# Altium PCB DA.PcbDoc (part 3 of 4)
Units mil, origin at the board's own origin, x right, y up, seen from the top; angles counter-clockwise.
Board outline 6588.03 x 5423.03 mil, 4 copper layers (Top Layer, GND, VCC, Bottom Layer); 506 components, 345 nets, 1676 pads, 350 vias.
Unrouted connection lines stored in the file: 30.
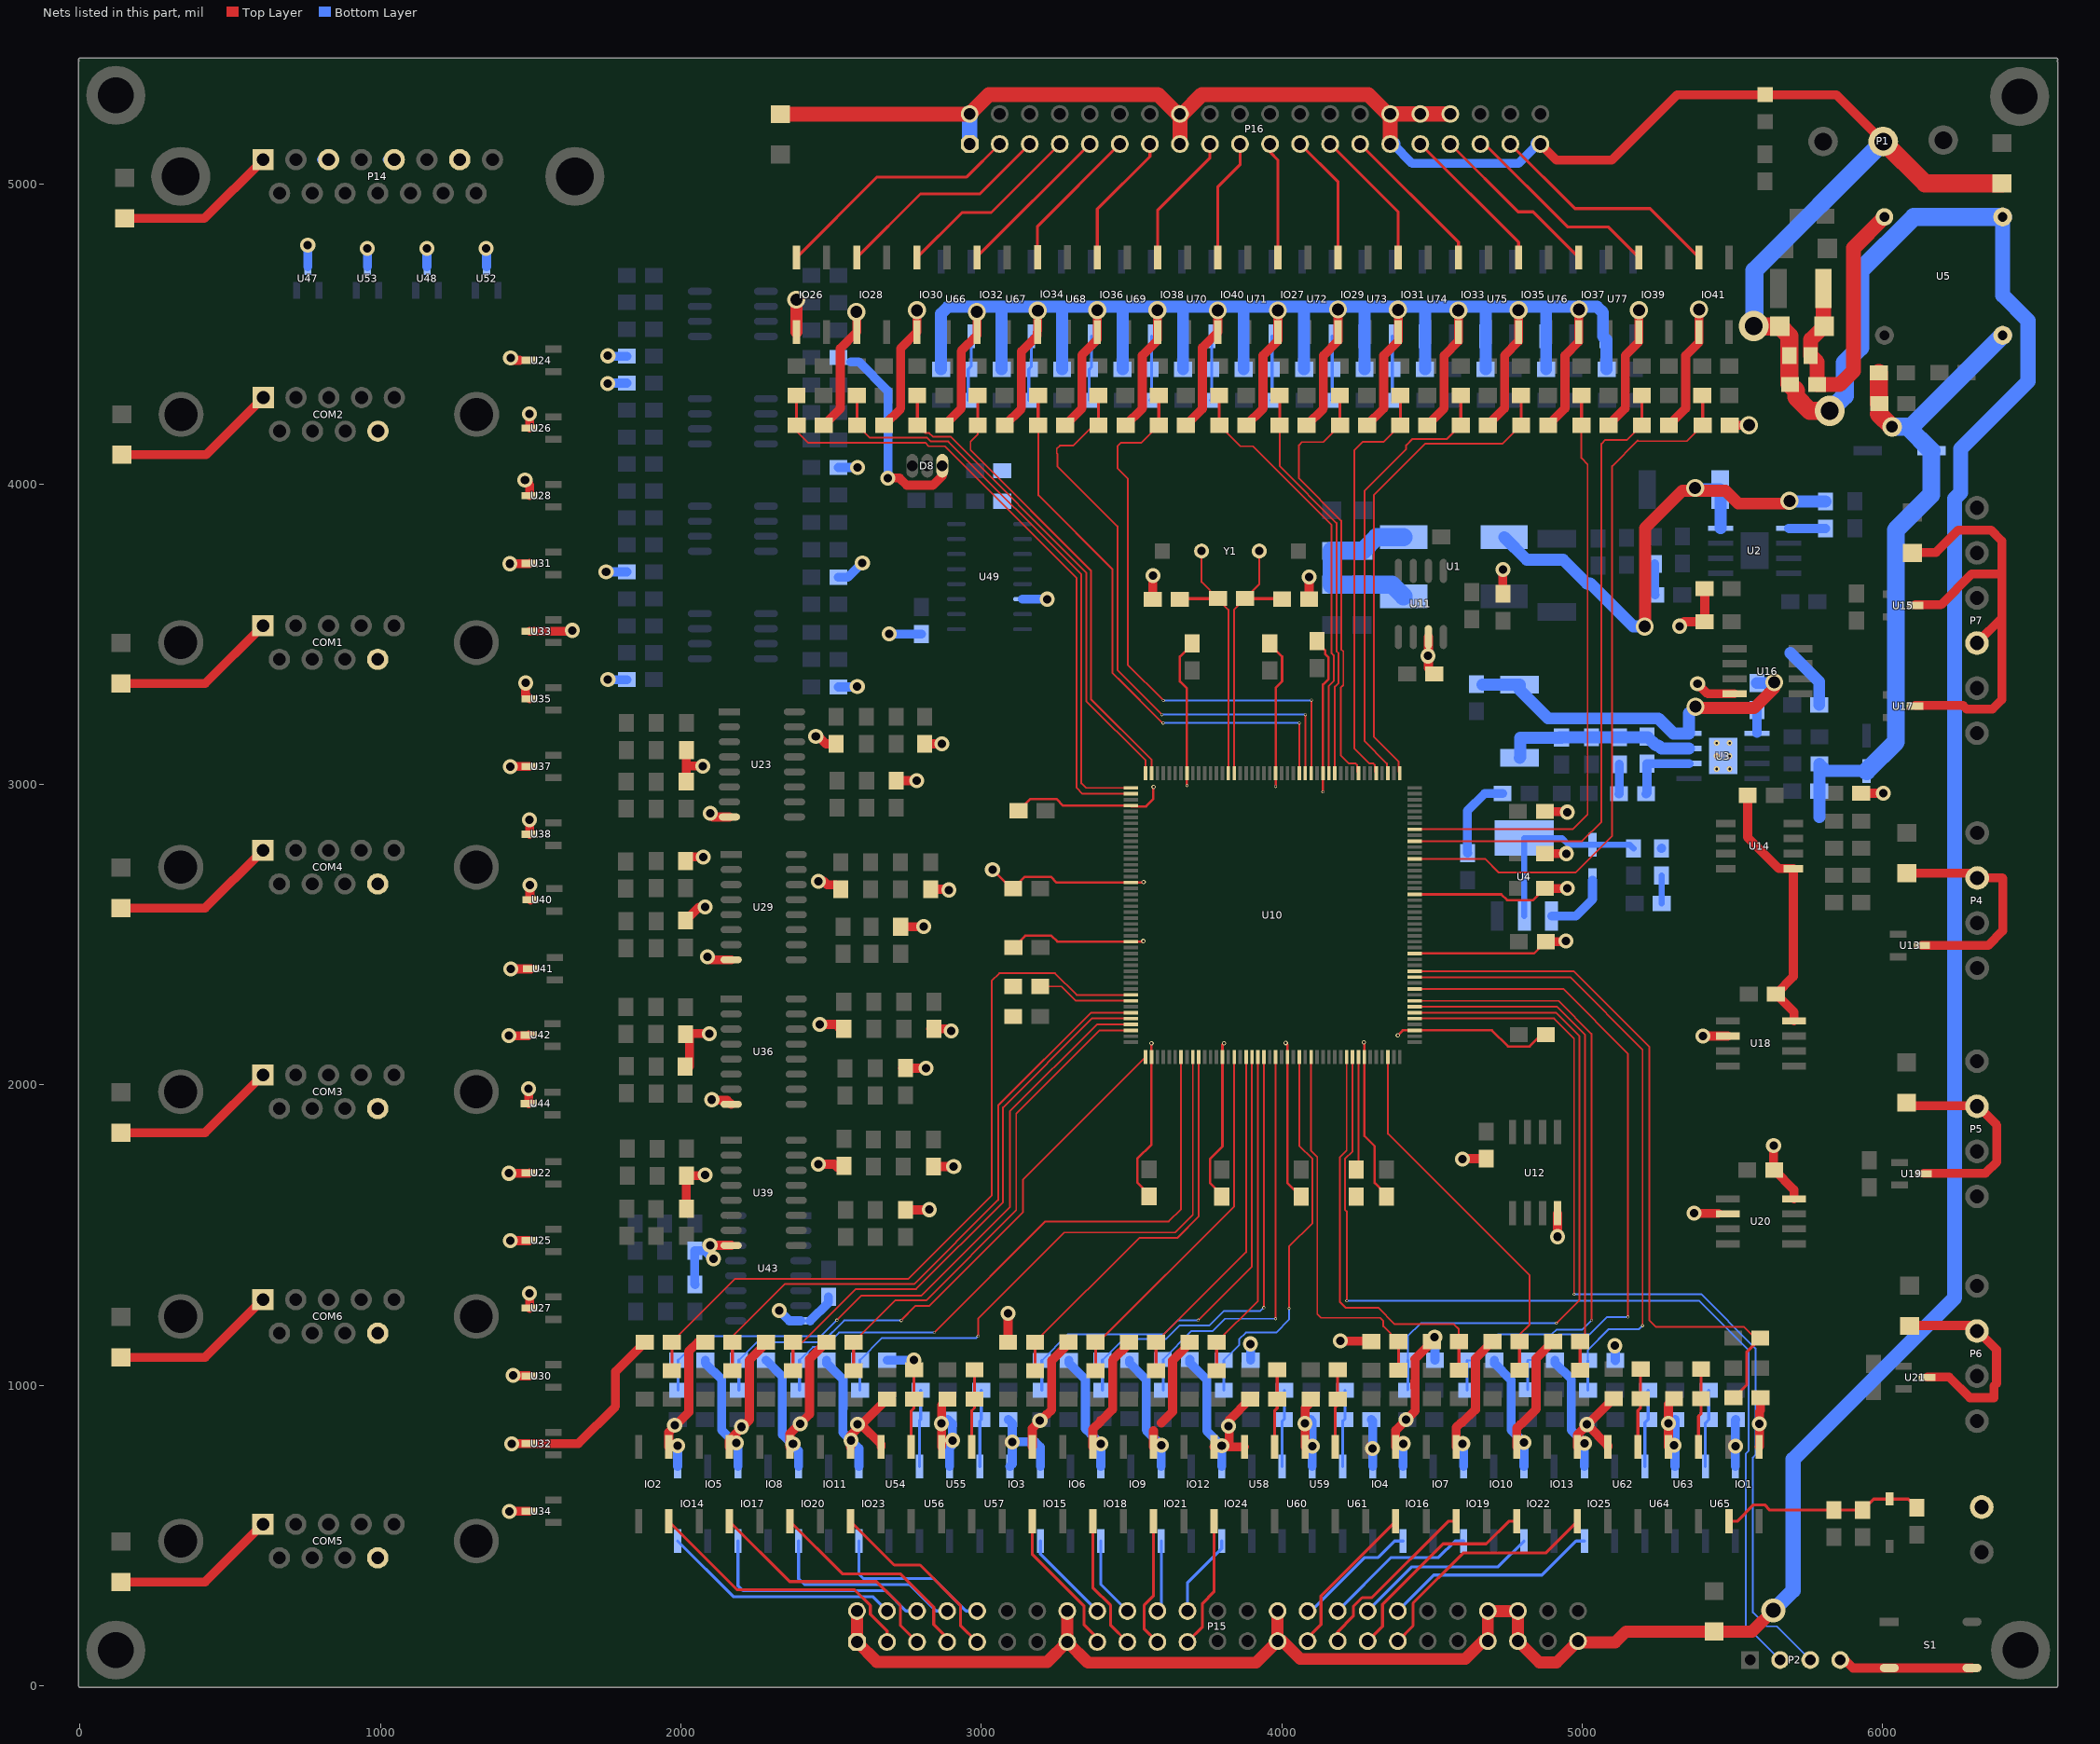
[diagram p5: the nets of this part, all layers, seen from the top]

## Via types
v1: diameter 10, hole 6, Top Layer to Bottom Layer, 112 vias
v2: diameter 50, hole 28, Top Layer to GND, 68 vias
v3: diameter 50, hole 28, Top Layer to Bottom Layer, 46 vias
v4: diameter 50, hole 28, GND to Bottom Layer, 36 vias
v5: diameter 15, hole 10, Top Layer to Bottom Layer, 28 vias
v6: diameter 60, hole 40, Top Layer to GND, 17 vias
v7: diameter 19.68, hole 7.87, Top Layer to Bottom Layer, 12 vias
v8: diameter 15, hole 8, Top Layer to GND, 8 vias
v9: diameter 60, hole 40, Top Layer to Bottom Layer, 7 vias
v10: diameter 34, hole 18, Top Layer to VCC, 4 vias
v11: diameter 10, hole 6, Top Layer to GND, 3 vias
v12: diameter 100, hole 60, Top Layer to Bottom Layer, 2 vias
v13: diameter 36, hole 20, Top Layer to VCC, 1 vias
v14: diameter 15, hole 8, Top Layer to VCC, 1 vias
v15: diameter 10, hole 6, Top Layer to VCC, 1 vias
v16: diameter 65, hole 40, Top Layer to Bottom Layer, 1 vias
v17: diameter 50, hole 28, Top Layer to VCC, 1 vias
v18: diameter 34, hole 18, VCC to Bottom Layer, 1 vias
v19: diameter 80, hole 50, Top Layer to Bottom Layer, 1 vias

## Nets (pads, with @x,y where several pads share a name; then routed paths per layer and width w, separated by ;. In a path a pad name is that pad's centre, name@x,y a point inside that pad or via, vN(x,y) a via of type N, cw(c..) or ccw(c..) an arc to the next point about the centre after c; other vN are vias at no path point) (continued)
GND: C1.2 C2.2 C4.2 C8.1 C9.1 C12.2 C13.1 C14.1 C15.1 C16.1 C17.1 C18.2 C19.2 C23.1 C24.1 C25.2 C26.2 C28.1 C29.1 C30.1 C31.1 C32.1 C34.1 C35.1 C36.1 C37.1 C38.1 C39.1 C40.1 C41.1 C42.1 C43.1 C44.1 C45.1 C46.1 C47.1 C48.1 C49.1 C50.2 C51.2 C52.2 C53.2 C54.2 C55.2 C56.2 C57.2 C58.1 C59.1 C60.1 C61.1 C62.1 C63.1 C64.2 C65.2 C66.2 C67.2 C68.2 C69.1 C70.1 C71.1 C72.1 C73.1 C74.1 C75.1 C76.1 C77.1 C78.1 C79.1 C80.1 C81.1 C82.1 C83.1 C84.1 C85.1 C86.1 C87.1 C88.1 C89.1 C90.1 C91.1 C92.1 C93.1 C94.1 C95.1 C96.1 C97.1 C98.1 C99.1 C100.1 C101.1 C102.1 C104.1 C105.1 C107.1 C108.1 C109.1 C110.1 C111.1 C112.1 C113.1 C114.1 C115.1 C116.1 C117.1 C118.1 C119.1 C120.1 C121.1 C122.1 C123.1 C124.1 C125.1 C126.1 C127.1 C128.1 C129.1 C130.1 C131.1 C132.1 C133.1 C134.1 C135.1 C136.1 C137.1 C138.1 COM1.1 COM1.9 COM2.1 COM2.9 COM3.1 COM3.9 COM4.1 COM4.9 COM5.1 COM5.9 COM6.1 COM6.9 D3.1 D8.1 IO1.4 IO2.4 IO3.4 IO4.4 IO5.4 IO6.4 IO7.4 IO8.4 IO9.4 IO10.4 IO11.4 IO12.4 IO13.4 IO14.4 IO15.4 IO16.4 IO17.4 IO18.4 IO19.4 IO20.4 IO21.4 IO22.4 IO23.4 IO24.4 IO25.4 IO26.4 IO27.4 IO28.4 IO29.4 IO30.4 IO31.4 IO32.4 IO33.4 IO34.4 IO35.4 IO36.4 IO37.4 IO38.4 IO39.4 IO40.4 IO41.4 L3.1 P2.4 P3.2 P4.2 P5.2 P6.2 P7.4 P14.1 P14.3 P14.5 P14.7 R8.1 R9.1 R10.1 R14.1 R20.1 R22.2 R32.2 R35.2 R38.2 R41.2 R44.2 R47.2 R50.2 R53.2 R56.2 R59.2 R62.2 R65.2 R68.2 R71.2 R74.2 R77.2 R80.2 R83.2 R84.1 R85.1 R93.1 R94.1 R101.1 R102.1 R109.1 R110.1 S1.2 U1.3 U1.4 U3.7 U3.9 U4.1 U5.4 U10.14 U10.22 U10.37 U10.48 U10.61 U10.71 U10.90 U10.102 U10.113 U10.126 U10.135 U10.148 U10.158 U11.3 U12.4 U13.3 U14.5 U15.3 U16.4 U17.3 U18.2 U18.8 U19.3 U20.2 U20.8 U21.3 U22.3 U23.8 U24.3 U25.3 U26.3 U27.3 U28.3 U29.8 U30.3 U31.3 U32.3 U33.3 U34.3 U35.3 U36.8 U37.3 U38.3 U39.8 U40.3 U41.3 U42.3 U43.8 U44.3 U47.3 U48.3 U49.14 U52.3 U53.3 U54.3 U55.3 U56.3 U57.3 U58.3 U59.3 U60.3 U61.3 U62.3 U63.3 U64.3 U65.3 U66.3 U67.3 U68.3 U69.3 U70.3 U71.3 U72.3 U73.3 U74.3 U75.3 U76.3 U77.3 | length 48606
  Top Layer w8: v2(3037,2716) 3099.06,2653.94 C38.1@3106,2653.94 3145,2692.94 3231.8,2692.94 3250.91,2673.83 U10.61@3497.33,2673.83 3538.29,2673.83 v8(3540.06,2675.6) ; C39.1@3107,2457.94 3146,2496.94 3232.8,2496.94 3252.76,2476.98 U10.71@3497.33,2476.98 3536.98,2476.98 v8(3539,2479) ; C37.1@3124,2912.94 3163,2951.94 3249.8,2951.94 3272,2929.73 U10.48@3497.33,2929.73 3500.02,2927.05 3547.99,2927.05 3572,2951.05 v8@3572,2990 ; C41.1@3558.06,1629 3558.06,1636 3519.06,1675 3519.06,1754.8 3566.23,1801.96 U10.90@3566.23,2093.12 v8(3566.23,2138.77) v8@3566,2139 ; v11@3684.34,2996.66 U10.37@3684.34,3038 3684.34,3319.97 3660.94,3343.37 3660.94,3426 3701.94,3467 C36.1@3701.94,3470 ; C42.1@3800.06,1628 3800.06,1635 3761.06,1674 3761.06,1753.8 3802.45,1795.18 U10.102@3802.45,2093.12 3802.45,2133.45 v8(3807.77,2138.77) ; C35.1@3959.94,3470 3959.94,3467 4000.94,3426 4000.94,3343.37 3979.61,3322.05 U10.22@3979.61,3038 v11@3979.61,2993.61 ; v8(4013,2140) 4018.98,2134.02 U10.113@4018.98,2093.12 4018.98,1673.08 C43.1@4064.06,1628 ; C34.1@4116.94,3477 4116.94,3474 4144,3446.94 4144,3434.73 4155.94,3422.8 4155.94,3351.2 4137.1,3332.36 U10.14@4137.1,3038 v11@4137.1,2975.1 ; v8(4273.23,2141.77) 4274.89,2140.11 U10.126@4274.89,2093.12 4274.89,1830.11 4309.06,1795.94 4309.06,1674 4348.06,1635 C44.1@4348.06,1628 ; v8(4386,2165) 4402.7,2181.7 U10.135@4442.21,2181.7 4699.56,2181.7 4753.2,2128.06 4824.8,2128.06 4863.8,2167.06 C45.1@4879,2167.06 ; U10.148@4442.21,2437.61 4839.54,2437.61 C46.1@4879,2477.06 ; U10.158@4442.21,2634.46 4730.81,2634.46 4750.2,2615.06 4837,2615.06 C47.1@4876,2654.06 ; v2@4944.06,2477.06 v2(4946,2479)
  Top Layer w30: C58.1@136,345.68 416.66,345.68 COM5.1@608.89,537.91 ; C59.1@136,1093.34 416.66,1093.34 COM6.1@608.89,1285.57 ; C60.1@136,1841.01 416.66,1841.01 COM3.1@608.89,2033.24 ; C61.1@136,2588.68 416.66,2588.68 COM4.1@608.89,2780.91 ; C62.1@136,3336.34 416.66,3336.34 COM1.1@608.89,3528.57 ; C63.1@139,4097.68 419.66,4097.68 COM2.1@609.89,4287.91 ; C72.1@148,4884.68 414,4884.68 P14.1@609.23,5079.91 ; v2(1427,2164) 1491.63,2164 U42.3@1493.63,2166 ; v2(1428,1706) 1494.87,1706 U22.3@1496.63,1707.76 ; v2(1429,580) 1430,581 U34.3@1496.63,581 ; v2(1431,3735) 1495.69,3735 U31.3@1496.63,3735.94 ; v2(1432,1482) 1496.22,1482 U25.3@1496.63,1482.41 ; v2(1432,3060) 1496.51,3060 U37.3@1496.63,3059.88 ; v2(1433,4420) 1441,4412 1463,4412 ; v2(1434,2386) 1500.63,2386 U41.3@1501.63,2387 ; v2(1437,805) 1438.35,806.35 U32.3@1496.63,806.35 1658.35,806.35 1782,930 1782,1045.94 C73.1@1880,1143.94 ; v2@1441.29,1031.71 U30.3@1496.63,1031.71 ; v2(1481,4013) 1496.63,3997.37 U28.3@1496.63,3961.29 ; v2(1483,3338) 1483,3298.86 U35.3@1496.63,3285.23 ; v2(1493,1987) 1493,1938.63 U44.3@1493.63,1938 ; v2(1496,1306) 1496,1257.69 U27.3@1496.63,1257.06 ; v2(1496,2883) 1496.63,2882.37 U38.3@1496.63,2834.53 ; v2(1496,4234) 1496.63,4233.37 U26.3@1496.63,4186.65 ; U33.3@1496.63,3510.59 1627.59,3510.59 v2@1628,3511 ; v2(1497,2665) 1497,2618.63 U40.3@1499.63,2616 ; IO2.4@1959.64,795.56 1959.64,844.18 2026.45,911 2026.45,1113.45 2056.94,1143.94 C76.1@2081.45,1143.94 ; R50.2@2015.01,2744.81 2029.2,2759 v2(2074,2759) ; R53.2@2015.29,2547.56 2059.73,2592 v2(2080,2592) ; R41.2@2017.63,3010 2017.94,3010.31 2017.94,3062 ; R38.2@2017.94,3115 2017.94,3062 ; R77.2@2019.06,1588 2018.19,1588.88 R74.2@2018.19,1698.25 2078.25,1698.25 v2(2080,1700) ; R65.2@2028.06,2061 2028.94,2061.87 2028.94,2171 v2(2094,2171) ; v2(2073,3061) 2072,3062 2017.94,3062 ; v2(2088,2426) 2097.19,2416.81 U29.8@2167.23,2416.81 ; v2(2097,1466) U39.8@2167.23,1466 ; v2@2098,2900 2106,2892 U23.8@2161.5,2892 ; v2(2103,1951) 2104.81,1949.19 2154.04,1949.19 U36.8@2167.23,1936 ; IO5.4@2161.26,795.56 2161.26,818.26 2227.91,884.91 2227.91,1084.29 2282.91,1139.29 C79.1@2282.91,1143.94 ; IO8.4@2362.89,795.56 2362.89,838.92 2427.91,903.94 2427.91,1087.48 C82.1@2484.36,1143.94 ; v2@2448.43,3160.65 2448.43,3161.43 2449.37,3162.37 2449.63,3162.37 2451,3161 2457.07,3161 2482.72,3135.36 C64.2@2516.5,3135.36 ; v2(2458,1736) 2510.44,1736 C67.2@2522.19,1724.25 ; v2(2458,2678) 2475.57,2678 2487.01,2666.56 2517.1,2666.56 C65.2@2532.1,2651.56 ; v2(2462,2202) 2462.5,2201.5 2515.93,2201.5 C66.2@2530.93,2186.5 ; C111.1@2475.41,4195.91 2530.58,4251.08 2530.58,4451.4 IO28.4@2585.18,4506 2585.18,4571.82 v6(2584,4573) ; IO11.4@2564.51,795.56 2564.51,832.63 v2@2600.94,869.06 ; v2@2599,871 v2@2600.94,869.06 ; U54.3@2666.14,795.56 2666.14,803.86 v2@2600.94,869.06 ; C117.1@2676.34,4195.91 2731.57,4251.14 2731.57,4452.11 IO30.4@2785.45,4506 v6(2785.45,4578.55) v6@2785,4579 ; C97.1@2685.82,953.94 v2@2600.94,869.06 ; v3(2689,4020) 2728.12,4020 2751.49,3996.63 2838.51,3996.63 2870,4028.12 D8.1@2870,4061 ; R35.2@2717.06,3013 v2(2785,3013) ; R47.2@2731.29,2526.81 v2(2808.19,2526.81) ; R59.2@2737.06,2056 v2(2816,2056) ; R71.2@2747.06,1584.25 2826.25,1584.25 v2(2827,1585) ; R32.2@2811.5,3135.36 v2(2868.64,3135.36) ; R44.2@2830.88,2651.35 2889.65,2651.35 v2(2892,2649) ; R56.2@2830.93,2186.93 v2@2893.07,2186.93 ; R68.2@2840.19,1728.25 2907.75,1728.25 v2(2908,1728) ; U55.3@2867.77,795.56 2867.77,934.43 C98.1@2887.27,953.94 ; C121.1@2877.28,4195.91 2932.55,4251.19 2932.55,4442.91 2985.73,4496.09 IO32.4@2985.73,4506 2985.73,4572.27 v6(2985,4573) ; C125.1@3078.21,4195.91 3133.54,4251.25 3133.54,4441.54 3186,4494 IO34.4@3186,4506 ; C74.1@3088.73,1143.94 3088.73,1239.73 v3(3089,1240) ; IO3.4@3169.39,795.56 3169.39,856.39 3216.94,903.94 3219.08,903.94 3234,918.85 3234,1083.11 3289.91,1139.02 C77.1@3289.91,1144.38 ; IO34.4@3187.73,4511 v6(3187.73,4577.27) ; C128.1@3279.14,4195.91 3334.53,4251.3 3334.53,4429.48 3386.27,4481.23 IO36.4@3386.27,4506 3386.27,4578.73 v6(3386,4579) ; IO6.4@3371.02,795.56 3371.02,854.42 3397.06,880.46 3397.06,883.94 ; 3398.8,882.2 3436.64,920.04 3436.64,1084.29 3491.64,1139.29 C80.1@3491.64,1143.94 ; C131.1@3480.08,4195.91 3535.52,4251.35 3535.52,4428.27 3586.55,4479.3 IO38.4@3586.55,4506 3586.55,4578.45 v6(3586,4579) ; C30.1@3571,3616.94 v2(3571,3696) ; IO9.4@3572.65,795.56 3572.65,848.65 ; 3599,875 3636.64,912.64 3636.64,1082.84 3693.09,1139.29 C83.1@3693.09,1143.94 ; C134.1@3681.01,4195.91 3735.52,4250.42 3735.52,4454.7 IO40.4@3786.82,4506 3786.82,4577.82 v6(3787,4578) ; IO12.4@3774.27,795.56 U58.3@3875.9,795.56 ; 3825,803 3825,884.39 C101.1@3894.55,953.94 ; C137.1@3881.94,4195.91 3937.49,4251.46 3937.49,4428.27 3987.09,4477.87 IO27.4@3987.09,4506 3987.09,4577.91 v6(3987,4578) ; U59.3@4077.52,795.56 4077.52,925.52 4096,944 C102.1@4096,953.94 ; C112.1@4082.88,4195.91 4138.48,4251.52 4138.48,4428.27 4187.36,4477.15 IO29.4@4187.36,4506 4187.36,4580.64 v6(4187,4581) ; C29.1@4091,3617.06 v2(4091,3691) ; v2(4194.99,1147.88) 4296.51,1147.88 C75.1@4298.45,1145.94 ; C118.1@4283.81,4195.91 4339.47,4251.57 4339.47,4428.27 4387.64,4476.44 IO31.4@4387.64,4506 4387.64,4579.36 v6(4387,4580) ; IO4.4@4379.15,795.56 4379.15,850.15 4443.45,914.45 4443.45,991.29 4443,991.75 4443,1015.13 4443.45,1015.58 4443.45,1086.29 4443,1086.75 4443,1088 4499.91,1144.91 C78.1@4499.91,1145.94 ; C122.1@4484.74,4195.91 4540.46,4251.63 4540.46,4428.27 4587.91,4475.72 IO33.4@4587.91,4506 v6(4587.91,4578.09) v6@4586,4580 ; U11.3@4488,3491 4488,3387.94 C26.2@4508,3367.94 ; IO7.4@4580.78,795.56 4580.78,860.78 4596,876 4600.33,876 4643.24,918.91 4644.91,918.91 4644.91,1089.48 C81.1@4701.36,1145.94 ; v2@4603,1755 C25.2@4679.94,1755 ; C126.1@4685.68,4195.91 4741.44,4251.68 4741.44,4428.27 4788.18,4475.01 IO35.4@4788.18,4506 4788.18,4578.82 v6(4788,4579) ; R14.1@4735.94,3635 v2(4735.94,3716.06) ; IO10.4@4782.4,795.56 4782.4,858.4 4795,871 4796.78,871 4846.36,920.58 4846.36,1089.48 C84.1@4902.82,1145.94 ; C47.1@4876,2654.06 v2@4949.06,2654.06 ; R20.1@4876,2770.06 4946.94,2770.06 v2(4947,2770) ; C48.1@4876,2910.06 4947.94,2910.06 v2(4950,2908) ; C46.1@4879,2477.06 v2@4944.06,2477.06 ; C129.1@4886.61,4195.91 4942.43,4251.74 4942.43,4428.27 4988.45,4474.29 IO37.4@4988.45,4506 4988.45,4580.45 v6(4989,4581) ; v2(4918.06,1494.94) U12.4@4918.06,1573 ; IO13.4@4984.03,795.56 4984.03,835.69 v2@5016.67,868.33 ; v2(5015.06,869.94) v2@5016.67,868.33 ; U62.3@5085.66,795.56 5085.66,799.34 v2@5016.67,868.33 ; C132.1@5087.54,4195.91 5143.42,4251.79 5143.42,4428.27 5188.73,4473.57 IO39.4@5188.73,4506 5188.73,4578.73 v6(5189,4579) ; C107.1@5104.27,955.94 v2@5016.67,868.33 ; U63.3@5287.28,795.56 5287.28,937.49 C108.1@5305.73,955.94 ; C135.1@5288.48,4195.91 5344.41,4251.85 5344.41,4428.27 5389,4472.86 IO41.4@5389,4506 v6(5389,4581) ; v2(5324,3527) 5339.06,3542.06 C50.2@5407,3542.06 ; v3(5372,1573) U20.2@5453,1573 ; v2@5390,3330 5418,3302 U16.4@5507,3302 ; v2(5402,2163) U18.2@5485,2163 ; C50.2@5408,3544.06 C51.2@5408,3654.06 ; C138.1@5491.41,4195.91 v6(5554.91,4195.91) ; C49.1@5551,2963.94 5551,2824 5654.94,2720.06 U14.5@5702.91,2720.06 5702.91,2360.85 C54.2@5645,2302.94 5705,2242.94 U18.8@5705,2213 ; IO1.4@5588.91,795.56 5590,796.65 5590,913 5593.91,916.91 C28.1@5593.91,958.51 ; v2(5637,1798) 5637,1718.94 C57.2@5639,1716.94 5705,1650.94 U20.8@5705,1621 ; P2.4@5859,86 5875,86 5901.54,59.46 S1.2@6022,59.46 S1.2@6297.59,59.46 ; R22.2@5929,2970.94 6001.94,2970.94 v2(6002,2971) ; C53.2@6081,1942.68 6092.68,1931 6315,1931 6380,1866 6380,1744 6342,1706 U19.3@6136.37,1706 ; C52.2@6081,2704.68 6299.32,2704.68 P4.2@6315,2689 6398,2689 6400,2687 6400,2513 6351,2464 U13.3@6130.37,2464 ; C55.2@6091,1199.68 6298.32,1199.68 6379.37,1118.63 6379.37,1006.34 6371,997.97 6371,959 6290,959 6221,1028 U21.3@6149.37,1028 ; C56.2@6100,3772.68 6177.68,3772.68 6252,3847 6361,3847 6397,3811 6397,3701 ; U17.3@6108.37,3263 6267.43,3263 6279.43,3251 6365,3251 6397,3283 6397,3555 ; U15.3@6108.37,3598 6194,3598 6297,3701 6397,3701 ; P7.4@6315,3473 6397,3555 ; 6397,3555 6397,3701
  Top Layer w40: v6(2384,4614) 2384.91,4613.09 IO26.4@2384.91,4506 ; v16@6030,4191 v16(6031,4191)
  Top Layer w60: 5987,4234 v16@6030,4191 ; C24.1@5987,4267.94 C23.1@5987,4369.94
  Bottom Layer w8: U43.8@2399,1215 U43.8@2430,1215
  Bottom Layer w30: U47.3@758,4723.37 v4(758,4795) ; P14.3@803.77,5079.91 P14.3@827.38,5079.91 P14.3@827.38,5091.06 ; v4(956,4785) 956.33,4784.67 U53.3@956.33,4723.37 ; P14.5@1021.93,5079.91 P14.5@1045.54,5079.91 ; U48.3@1154.67,4723.37 1154.67,4784.67 v4(1155,4785) ; P14.7@1263.69,5079.91 P14.7@1263.69,5082.31 ; v4(1352,4785) 1353,4784 U52.3@1353,4723.37 ; v4(1750.89,3707.89) R109.1@1820,3707.89 ; v4(1756,4334) 1754,4334 1752,4336 R94.1@1820,4336.02 ; v4@1756.05,3348.95 R93.1@1820,3348.95 ; v4(1757,4427) 1752.25,4427 1751,4425.75 R110.1@1820,4425.75 ; IO14.4@1989,730.06 v4(1989,799.06) ; R83.2@2046.94,1336 2046.06,1336.87 R80.2@2046.06,1448 2079.85,1448 2105.85,1422 v4(2109,1422) ; C85.1@2081,1084 2081,1074.36 2136,1019.36 2136,850.92 2150.92,836 2151.06,836 2190.24,796.83 IO17.4@2190.24,730.06 ; C88.1@2283,1084 2337.76,1029.24 2337.76,921.56 2337.56,921.36 2337.56,836 2391.47,782.09 IO20.4@2391.47,730.06 ; v4(2327,1249) 2361,1215 U43.8@2399,1215 ; U43.8@2430,1215 2491.06,1276.06 C68.2@2491.06,1295 ; C91.1@2485,1084 2485,1073.88 2539.53,1019.36 2539.53,922.05 2538.83,921.36 2538.83,844.23 2592.71,790.36 IO23.4@2592.71,730.06 ; R84.1@2524,3324.82 2585.82,3324.82 v4@2586,3325 ; R101.1@2524,3690.19 2556.19,3690.19 v4@2603.5,3737.5 ; R85.1@2524,4055.56 2588.44,4055.56 v4@2589,4055 ; 2565.22,4407 2592,4407 2689,4310 v3(2689,4020) ; C94.1@2686,1084 v4(2776,1084) ; v4@2691,3499 v4(2693,3501) C69.1@2800.94,3501 ; C99.1@2888,887 2903.06,871.94 2903.06,801.12 2893.94,792 U56.3@2893.94,730.06 ; C100.1@3090,886 3103.06,872.94 v4(3103.06,812.01) ; U57.3@3095.18,730.06 3103.06,737.95 v4(3103.06,812.01) ; U49.14@3137.24,3617 v4(3219,3617) v4@3220,3616 ; IO15.4@3196.41,730.06 3196.41,794.65 3179.06,812.01 v4(3103.06,812.01) ; C86.1@3291,1083 3291,1074.94 3346.59,1019.36 3346.59,855.7 3363,839.29 3363.78,839.29 v4(3397.65,805.42) IO18.4@3397.65,730.06 ; C89.1@3493,1084 3493,1074.71 3548.35,1019.36 3548.35,850.71 v4(3598.88,800.18) IO21.4@3598.88,730.06 ; C92.1@3694,1086 3694,1075.47 3750.12,1019.36 3750.12,848.95 v4(3800.12,798.95) IO24.4@3800.12,730.06 ; C95.1@3896,1084 v4(3896,1138.06) ; C104.1@4096,886 4101.35,880.65 U60.3@4101.35,730.06 ; C105.1@4298,886 4302.59,881.41 U61.3@4302.59,730.06 ; IO16.4@4403.82,730.06 4403.82,805.89 v4(4404,806.06) ; v4(4509,1160.06) 4509.82,1159.25 C87.1@4509.82,1084 ; v4@4603,804.06 4603,796.06 4605.06,794.01 IO19.4@4605.06,730.06 ; C18.2@4618.29,2772 C18.2@4617.94,2772 4617.94,2912.94 4675.06,2970.06 R10.1@4734.81,2970.06 ; C90.1@4708.15,1084 4708.15,1073.2 4763,1018.36 4763,851.64 4778.64,836 4780.06,836 v4(4806.29,809.77) IO22.4@4806.29,730.06 ; U4.1@4898,2562.13 4978.13,2562.13 5034,2618 C19.2@5034,2681.89 ; C93.1@4909,1084 4909,1075.36 4964,1020.36 4964,851.06 v4(5007.53,807.54) IO25.4@5007.53,730.06 ; v4(5109,1132.06) 5110,1131.06 C96.1@5110,1083 ; L3.1@5264,2787.27 L3.1@5265,2788.27 ; U64.3@5308.76,730.06 5308.76,885.04 C109.1@5309.72,886 ; U65.3@5510,730.06 5510,885 C110.1@5511,886
  Bottom Layer w40: C113.1@2866.09,4382.06 U66.3@2866.09,4492 2866.09,4567.09 2889,4590 3269,4590 ; C114.1@3067.45,4382.06 3067.45,4588.55 ; C115.1@3268.82,4382.06 3268.82,4489.82 3269,4490 3269,4590 ; C116.1@3470.18,4382.06 3470.18,4588.82 3469,4590 ; C119.1@3671.55,4382.06 3671.55,4585.45 ; C120.1@3872.91,4382.06 3872.91,4586.09 3869,4590 ; C123.1@4074.27,4382.06 4074.27,4589.27 4075,4590 ; C124.1@4275.64,4382.06 4275.64,4588.36 4274,4590 ; C127.1@4477,4382.06 4477,4583 4470,4590 ; C130.1@4678.36,4382.06 4678.36,4588.64 4677,4590 ; D3.1@4792,3089.35 4794,3091.35 4794,3156 C16.1@4930.88,3156 ; C133.1@4879.73,4382.06 4879.73,4588.73 4881,4590 ; C16.1@4924.45,3157 C17.1@5030.88,3157 C13.1@5123.88,3157 5218.88,3157 5245.88,3130 5253.3,3130 5263.3,3120 U3.7@5355.62,3120 ; C136.1@5081.09,4382.06 5081.09,4480 U77.3@5069.09,4492 5069.09,4570.91 5050,4590 4881,4590 ; 5692.81,3438 5788.81,3342 C15.1@5788.81,3264.94 ; 5788.81,2891 5789.81,2892 R9.1@5789.81,3068.94 5813.86,3044.89 C12.2@5946.81,3044.89 ; 3269,4590 3469,4590 ; 3469,4590 3869,4590 ; 3869,4590 4075,4590 ; 4075,4590 4274,4590 ; 4274,4590 4470,4590 ; 4470,4590 4677,4590 ; 4677,4590 4881,4590
  Bottom Layer w60: U1.3@4405.68,3626.57 4366.61,3665.65 C2.2@4267,3665.65 C1.2@4166,3665.65 C8.1@4166,3778 C9.1@4270,3778 4315.43,3823.43 U1.4@4405.68,3823.43 ; C12.2@5946.81,3044.89 6044,3142.08 6044,3847 6162,3965 6162,4110.7 C4.2@6162.3,4111 6082.3,4191 ; v16(6031,4191) 6082.3,4191 ; U5.4@6399.7,4495.3 6095.4,4191 6082.3,4191
  other v2: 2202,862 3823.06,863.94 1979,867 2588,871 2397,872 5590.06,871.94 2867.06,872.94 4077.06,872.94 5287.06,873.94 3195.06,882.94 4414.06,885.94 1442,1033 4601,1753 2900,2180 4950,2655 2098,2904 2449,3160 5384,3336 4486,3428 1638,3513
  other v4: 4302.59,790 4101.35,798 5511,798.06 5306,801.06 2373,805.06 4602,806.06 2185,809.06 2566,817.06 2904,817 2587,3326 1757,3350 2604,3737 2588,4055
  other v7: 5447.16,3051.69 5490.46,3051.69 5447.16,3095 5490.46,3095 5447.16,3138.31 5490.46,3138.31
  other v8: 3573.23,2991.77
  other v11: 4136.92,2975.65 3978.92,2993.65 3684.92,2996.65
I_01: C111.2 R179.2 U10.46 | length 2140.2
  Top Layer w6: C111.2@2384.59,4196.73 C111.2@2385.41,4195.91 2385.41,4175.59 2423,4138 2813,4138 2825.09,4125.91 2878.09,4125.91 3317,3687 3317,2989 3336.9,2969.1 U10.46@3497.33,2969.1
  Top Layer w10: C111.2@2384.59,4196.73 R179.2@2384.59,4294.91
I_02: C117.2 R187.2 U10.45 | length 1917.4
  Top Layer w6: R187.2@2585.58,4294.91 R187.2@2586.34,4294.15 ; C117.2@2586.34,4195.91 2628.26,4154 2819.63,4154 2831.71,4141.91 2890.09,4141.91 3333,3699 3333,3004 3348.21,2988.79 U10.45@3497.33,2988.79
  Top Layer w10: C117.2@2586.34,4195.91 R187.2@2586.34,4294.15
I_03: C121.2 R193.2 U10.44 | length 1613.6
  Top Layer w6: R193.2@2786.57,4294.91 R193.2@2787.28,4294.2 ; C121.2@2787.28,4195.91 2813.19,4170 2826.25,4170 2838.34,4157.91 2896.71,4157.91 3349,3705.63 3349,3277.55 3546.55,3080 U10.44@3546.55,3038
  Top Layer w10: C121.2@2787.28,4195.91 R193.2@2787.28,4294.2
I_04: C125.2 R199.2 U10.43 | length 1516.7
  Top Layer w6: R199.2@2987.55,4294.91 R199.2@2988.21,4294.26 ; C125.2@2988.21,4195.91 2988.21,4166.21 2964,4142 2964,4113.25 3365,3712.25 3365,3284.17 3566.23,3082.94 U10.43@3566.23,3038
  Top Layer w10: C125.2@2988.21,4195.91 R199.2@2988.21,4294.26
I_05: C128.2 R204.2 U10.18 | length 1882.9
  Top Layer w6: C128.2@3189.14,4195.91 3190.31,4194.74 3190.31,3962.31 3437,3715.63 3437,3371 3454.81,3353.19 3455,3353.19 3603.54,3204.65 v1(3605,3204.65) ; U10.18@4058.35,3038 v1(4058.35,3204.65)
  Top Layer w10: C128.2@3189.14,4195.91 R204.2@3189.14,4294.31
  Bottom Layer w6: v1(3605,3204.65) v1(4058.35,3204.65)
I_06: C131.2 R209.2 U10.17 | length 1972.7
  Top Layer w6: R209.2@3389.53,4294.91 R209.2@3390.08,4294.37 ; C131.2@3390.08,4195.91 3373.91,4195.91 3306,4128 3261.54,4128 3251,4117.46 3251,4102.54 3253,4100.54 3253,4059.37 3453,3859.37 3453,3380.65 v1(3601,3232.65) ; U10.17@4078.04,3038 4078.35,3038.31 v1(4078.35,3232.65)
  Top Layer w10: C131.2@3390.08,4195.91 R209.2@3390.08,4294.37
  Bottom Layer w6: v1(3601,3232.65) v1(4078.35,3232.65)
I_07: C134.2 R214.2 U10.16 | length 1911.6
  Top Layer w6: R214.2@3590.52,4294.91 R214.2@3591.01,4294.42 ; C134.2@3591.01,4195.91 3532.1,4137 3463.54,4137 3453,4126.46 3453,4053 3487,4019 3487,3399 v1(3606,3280) ; U10.16@4097.73,3038 4098.35,3038.63 v1(4098.35,3280.65)
  Top Layer w10: C134.2@3591.01,4195.91 R214.2@3591.01,4294.42
  Bottom Layer w6: v1(3606,3280) 3606.35,3279.65 4097.35,3279.65 v1(4098.35,3280.65)
I_08: C137.2 R219.2 U10.13 | length 1446.3
  Top Layer w6: R219.2@3791.51,4294.91 R219.2@3791.94,4294.48 ; C137.2@3791.94,4195.91 3861.86,4126 3904,4126 4166,3864 4166,3436.78 4172.94,3429.84 4172.94,3344.16 4156.78,3328 U10.13@4156.78,3038
  Top Layer w10: C137.2@3791.94,4195.91 R219.2@3791.94,4294.48
I_09: C112.2 R180.2 U10.12 | length 1343.4
  Top Layer w6: R180.2@3992.49,4294.91 R180.2@3992.88,4294.53 ; C112.2@3992.88,4195.91 3993.31,4195.48 3993.31,4059.31 4182,3870.63 4182,3443.4 4188.94,3436.47 4188.94,3337.53 4177,3325.6 4177,3304.61 4176.47,3304.08 U10.12@4176.47,3038
  Top Layer w10: C112.2@3992.88,4195.91 R180.2@3992.88,4294.53
I_10: C118.2 R188.2 U10.8 | length 1457.2
  Top Layer w6: C118.2@4193.81,4195.91 4137.9,4140 4067.54,4140 4057,4129.46 4057,4019.37 4198,3878.37 4198,3450.03 4204.94,3443.1 4204.94,3330.9 4196,3321.97 4196,3097.2 4222.58,3070.62 4245.15,3070.62 4250.43,3065.35 4250.43,3042.78 U10.8@4255.2,3038
  Top Layer w10: C118.2@4193.81,4195.91 R188.2@4193.81,4294.59
I_11: C122.2 R194.2 U10.5 | length 1399.9
  Top Layer w6: U10.5@4314.26,3038 4309.48,3042.78 4309.48,3065.35 4304.21,3070.62 4290.41,3070.62 4241,3120.03 4241,4112.46 4269.54,4141 4339.83,4141 C122.2@4394.74,4195.91
  Top Layer w10: C122.2@4394.74,4195.91 R194.2@4394.74,4294.64
I_12: C126.2 R200.2 U10.3 | length 1489.6
  Top Layer w6: U10.3@4353.63,3038 4349.94,3041.69 4349.94,3070.14 4275,3145.09 4275,3977.25 4414,4116.25 4414,4129.46 4434.54,4150 4549.76,4150 C126.2@4595.68,4195.91
  Top Layer w10: C126.2@4595.68,4195.91 R200.2@4595.68,4294.69
I_13: C129.2 R205.2 U10.1 | length 1646.1
  Top Layer w6: U10.1@4393,3038 4389.31,3041.69 4389.31,3076.03 4307,3158.34 4307,3964 4477,4134 4734.7,4134 C129.2@4796.61,4195.91
  Top Layer w10: C129.2@4796.61,4195.91 R205.2@4796.61,4294.75
I_14: C132.2 R210.2 U10.169 | length 1999.4
  Top Layer w6: U10.169@4442.21,2850.99 4968.99,2850.99 5018,2900 5018,4066 4997.54,4086.46 C132.2@4997.54,4195.91
  Top Layer w10: C132.2@4997.54,4195.91 R210.2@4997.54,4294.8
I_15: C135.2 R215.2 U10.167 | length 2165.5
  Top Layer w6: U10.167@4442.21,2811.62 4999.62,2811.62 5064,2876 5064,4134 5077,4147 5149.56,4147 C135.2@5198.48,4195.91
  Top Layer w10: C135.2@5198.48,4195.91 R215.2@5198.48,4294.86
I_16: C138.2 R220.2 U10.164 | length 2416.3
  Top Layer w6: U10.164@4442.21,2752.57 4676.81,2752.57 4722.37,2707 4978,2707 5099.82,2828.82 5099.82,4059.82 5183,4143 ; 5185.41,4145.41 5183,4143 ; C138.2@5401.41,4195.91 5348.5,4143 5183,4143
  Top Layer w10: C138.2@5401.41,4195.91 R220.2@5401.41,4292.91
I_EM: C28.2 R18.2 U10.145 | length 2425.6
  Top Layer w6: U10.145@4442.21,2378.55 4971.45,2378.55 5224,2126 5224,1216 5245,1195 5467.15,1195 5467.52,1195.38 5538.29,1195.38 5576.29,1157.38 R18.2@5592.91,1157.38
  Top Layer w10: C28.2@5503.91,958.51 5547.91,1002.51 5547.91,1112.38 R18.2@5592.91,1157.38
I_ERR1: C82.2 R138.2 U10.86 | length 1635.8
  Top Layer w6: C82.2@2574.36,1143.94 2713.43,1283 2816,1283 3116,1583 3116,1904 3393.7,2181.7 U10.86@3497.33,2181.7
  Top Layer w10: R138.2@2574.36,1049 C82.2@2574.36,1143.94
I_ERR2: C94.2 R162.2 U10.97 | length 1967.3
  Top Layer w6: v1(2989,1164) 2989,1222 3276,1509 3645,1509 3704.02,1568.03 U10.97@3704.02,2093.12
  Bottom Layer w6: C94.2@2596,1084 2670,1158 2983,1158 v1(2989,1164)
  Bottom Layer w10: R162.2@2596,984.29 C94.2@2596,1084
I_ERR3: C83.2 R139.2 U10.108 | length 1101.1
  Top Layer w6: C83.2@3783.09,1143.94 3920.56,1281.41 U10.108@3920.56,2093.12
  Top Layer w10: R139.2@3783.09,1049 C83.2@3783.09,1143.94
I_ERR4: C95.2 R163.2 U10.115 | length 1308.5
  Top Layer w6: v1(4024,1256) 4024,1461.94 4102.06,1540 4102.06,1753.38 4058.35,1797.09 U10.115@4058.35,2093.12
  Bottom Layer w6: C95.2@3806.88,1083.12 3858,1134.24 3858,1153.8 3880.26,1176.06 3981.06,1176.06 4024,1219 v1(4024,1256)
  Bottom Layer w10: R163.2@3806.88,984 C95.2@3806.88,1083.12
I_ERR5: C84.2 R140.2 U10.139 | length 1728.8
  Top Layer w6: U10.139@4442.21,2260.44 4916.56,2260.44 5009,2168 5009,1162.12 C84.2@4992.82,1145.94
  Top Layer w10: R140.2@4992.82,1050.94 C84.2@4992.82,1145.94
I_ERR6: C96.2 R164.2 U10.144 | length 2127
  Top Layer w6: U10.144@4442.21,2358.87 4959.87,2358.87 5201,2117.73 v1(5201,1199)
  Bottom Layer w6: C96.2@5019,1082 5019,1118 5088,1187 5189,1187 v1(5201,1199)
  Bottom Layer w10: R164.2@5019,984 C96.2@5019,1082
I_HOM1: C79.2 R132.2 U10.84 | length 1849.8
  Top Layer w6: C79.2@2372.91,1143.94 2404.94,1143.94 2582,1321 2782.63,1321 3072,1610.37 3072,1925 3368.07,2221.07 U10.84@3497.33,2221.07
  Top Layer w10: R132.2@2372.91,1049 C79.2@2372.91,1143.94
I_HOM2: C91.2 R156.2 U10.95 | length 2084.4
  Top Layer w6: v1(2844,1176) 2844,1177 3213,1546 3624,1546 3664.65,1586.66 U10.95@3664.65,2093.12
  Bottom Layer w6: C91.2@2395,1084 2439,1128 2478.08,1128 2526.08,1176 v1(2844,1176)
  Bottom Layer w10: R156.2@2394.53,984 C91.2@2394.53,1083.53
I_HOM3: C80.2 R133.2 U10.106 | length 1168.2
  Top Layer w6: C80.2@3581.64,1143.94 3881.19,1443.49 U10.106@3881.19,2093.12
  Top Layer w10: R133.2@3581.64,1049 C80.2@3581.64,1143.94
I_HOM4: C92.2 R157.2 U10.111 | length 1406.4
  Top Layer w6: v1@3979.61,1222 U10.111@3979.61,2093.12
  Bottom Layer w6: C92.2@3605.12,1084.88 C92.2@3604,1086 3699,1181 3770,1181 3811,1222 v1(3979,1222) ; C92.2@3625,1085.03 C92.2@3626.03,1084
  Bottom Layer w10: R157.2@3605.12,984 C92.2@3605.12,1084.88
I_HOM5: C81.2 R134.2 U10.130 | length 1251.7
  Top Layer w6: U10.130@4353.63,2093.12 4353.63,1837.37 4825.36,1365.64 4825.36,1202.54 4791.36,1168.54 C81.2@4791.36,1145.94
  Top Layer w10: R134.2@4791.36,1050.94 C81.2@4791.36,1145.94
I_HOM6: C93.2 R158.2 U10.142 | length 2164.2
  Top Layer w6: U10.142@4442.21,2319.5 4936.5,2319.5 5152,2104 v1(5152,1228)
  Bottom Layer w6: C93.2@4819,1084 4835.62,1084 4921.62,1170 5025,1170 5083,1228 v1(5152,1228)
  Bottom Layer w10: R158.2@4819,985 C93.2@4819,1081.48
I_LIM1+: C73.2 R120.2 U10.80 | length 2579.1
  Top Layer w6: C73.2@1970,1143.94 2181.06,1355 2757,1355 3034,1632 3034,2346 3060,2372 3245,2372 3317.19,2299.81 U10.80@3497.33,2299.81
  Top Layer w10: R120.2@1970,1049 C73.2@1970,1143.94
I_LIM1-: C76.2 R126.2 U10.83 | length 2071.1
  Top Layer w6: C76.2@2171.45,1143.94 2171.45,1163.45 2345,1337 2776,1337 3056,1617 3056,1931.63 3365.37,2241 3497.09,2241 U10.83@3497.33,2240.76
  Top Layer w10: R126.2@2171.45,1049 C76.2@2171.45,1143.94
I_LIM2+: C85.2 R144.2 U10.85 | length 2256
  Top Layer w6: v1(2519,1217) 2601,1299 2801,1299 3095,1593 3095,1912 3384.39,2201.39 U10.85@3497.33,2201.39
  Bottom Layer w6: C85.2@1991,1084 2071,1164 2466,1164 v1(2519,1217)
  Bottom Layer w10: R144.2@1991,984 C85.2@1991,1084
I_LIM2-: C88.2 R150.2 U10.89 | length 1935.2
  Top Layer w6: v1@2732.5,1216.5 2781,1265 2827,1265 3138,1576 3138,1684.57 U10.89@3546.55,2093.12
  Bottom Layer w6: C88.2@2193,1084 2253,1144 2471.46,1144 2543.46,1216 v1(2733,1216)
  Bottom Layer w10: R150.2@2192.76,984 C88.2@2192.76,1083.76
I_LIM3+: C74.2 R121.2 U10.98 | length 1343.8
  Top Layer w6: C74.2@3178.73,1143.94 3525.79,1491 3652,1491 3723.71,1562.71 U10.98@3723.71,2093.12
  Top Layer w10: R121.2@3178.73,1049 C74.2@3178.73,1143.94
I_LIM3-: C77.2 R127.2 U10.104 | length 1241.1
  Top Layer w6: C77.2@3379.91,1144.38 3389.83,1144.38 3841.82,1596.37 U10.104@3841.82,2093.12
  Top Layer w10: R127.2@3380.18,1049 C77.2@3380.18,1144.17
I_LIM4+: C86.2 R145.2 U10.107 | length 1626
  Top Layer w6: v1(3722,1217) 3900.88,1395.88 U10.107@3900.88,2093.12
  Bottom Layer w6: C86.2@3201.59,1082.41 C86.2@3201,1083 3288,1170 3608,1170 3655,1217 v1(3722,1217)
  Bottom Layer w10: R145.2@3201.59,984 C86.2@3201.59,1082.41
I_LIM4-: C89.2 R151.2 U10.109 | length 1543.9
  Top Layer w6: v1@3940.24,1259.24 U10.109@3940.24,2093.12
  Bottom Layer w6: R151.2@3403,984.35 R151.2@3403.35,984 ; C89.2@3403,1084 3473,1154 3614.63,1154 3659.63,1199 3759,1199 3807,1247 3928,1247 v1(3940,1259) ; C89.2@3426.71,1084 C89.2@3427,1084.29
  Bottom Layer w10: R151.2@3403,984.35 C89.2@3403,1084
I_LIM5+: C75.2 R122.2 U10.117 | length 1278.2
  Top Layer w6: U10.117@4097.73,2093.12 4097.73,1780.35 4118.06,1760.01 4118.06,1236.94 4130,1225 4327.46,1225 4338,1214.46 4338,1196.45 C75.2@4388.45,1146
  Top Layer w10: R122.2@4388.45,1050.94 C75.2@4388.45,1145.94
I_LIM5-: C78.2 R128.2 U10.123 | length 1393.2
  Top Layer w6: U10.123@4215.84,2093.12 4215.84,1781.78 4194.06,1760.01 4194.06,1332.06 4194,1332 4194,1277 4212,1259 4321,1259 4376,1204 4573,1204 4589,1188 C78.2@4589,1146.84
  Top Layer w10: R128.2@4589.91,1050.94 C78.2@4589.91,1145.94
I_LIM6+: C87.2 R146.2 U10.138 | length 2260.9
  Top Layer w6: U10.138@4442.21,2240.76 4912.24,2240.76 4991,2162 4991,1284 v1(4914,1207)
  Bottom Layer w6: R146.2@4418,984 R146.2@4419.82,985.82 ; C87.2@4419.82,1084 4419.82,1163.82 4463,1207 v1(4914,1207)
  Bottom Layer w10: R146.2@4419.82,985.82 C87.2@4419.82,1084
I_LIM6-: C90.2 R152.2 U10.140 | length 2155.8
  Top Layer w6: U10.140@4442.21,2280.13 4442.34,2280 4921,2280 5030.69,2170.31 v1(5030.69,1216.31)
  Bottom Layer w6: C90.2@4617,1082.85 4633.62,1082.85 4720.77,1170 4898.99,1170 4914.99,1186 5000.37,1186 v1(5030.69,1216.31)
  Bottom Layer w10: R152.2@4617,984 C90.2@4617,1082.85
IO_GND: C10.2 C22.1 C103.1 C106.1 D5.1 D6.2 P1.2 P15.1 P15.2 P15.15 P15.16 P15.29 P15.30 P15.43 P15.44 P15.45 P15.46 P15.49 P16.1 P16.2 P16.15 P16.16 P16.29 P16.30 P16.32 P16.34 P16.39 R13.1 U5.2 | length 16133.1
  Top Layer w30: P16.39@4861,5132 4915,5078 5098,5078 5316,5296 D6.2@5609,5296 5846,5296 P1.2@6002,5140
  Top Layer w40: P15.2@2586,249 P15.1@2586,146 2652,80 3220,80 P15.15@3286,146 ; P15.16@3286,249 P15.15@3286,146 ; P15.30@3986,249 P15.29@3986,149 ; v19(5636,251) 5565.68,180.68 C103.1@5439,180.68 5145.68,180.68 5110,145 4990,145 P15.49@4986,149 4915,78 4857,78 P15.45@4786,149 P15.46@4786,249 P15.44@4686,249 P15.43@4686,149 4670.18,149 4610.66,89.47 4061.34,89.47 4001.82,149 P15.29@3986,149 ; P15.15@3286,146 3355,77 3914,77 P15.29@3986,149
  Top Layer w50: C106.1@2331,5231.32 2960.32,5231.32 P16.2@2961,5232 3025.53,5296.53 3587.73,5296.53 3652.26,5232 P16.16@3661,5232 ; P16.15@3661,5132 P16.16@3661,5232 ; P16.29@4361,5132 P16.30@4361,5232 ; P16.34@4561,5232 P16.32@4461,5232 P16.30@4361,5232 ; U5.2@6397,4891.7 U5.2@6399.7,4889 ; P16.16@3661,5232 3669.74,5232 3734.27,5296.53 4287.73,5296.53 4352.26,5232 P16.30@4361,5232
  Top Layer w60: v12(5571,4526) 5572,4525 D5.1@5657.57,4525 5689.57,4493.01 R13.1@5689.57,4428 C22.1@5689.57,4333.37 ; C22.1@5692,4330.94 5712,4310.94 5712,4289.37 5757.37,4244 v12(5824,4244) ; P1.2@6002,5140 6141.32,5000.68 C10.2@6397,5000.68
  Bottom Layer w30: P16.29@4369.74,5132 4434.27,5067.47 4787.73,5067.47 P16.39@4852.26,5132
  Bottom Layer w50: P16.1@2961,5132 P16.2@2961,5232 ; P16.29@4361,5132 P16.29@4369.74,5132 ; P16.39@4852.26,5132 P16.39@4861,5132 ; v19(5636,251) 5702,317 5702,754 6239.63,1291.63 6239.63,3951.81 6260,3972.18 6260,4118 6484,4342 6484,4544 6399.7,4628.3 U5.2@6399.7,4889
  Bottom Layer w60: v12@5573,4526 5573,4711 P1.2@6002,5140 ; v12(5824,4244) 5874,4294 5874,4403.99 5925,4454.99 5925,4709.67 6104.33,4889 U5.2@6399.7,4889
JTCK: P2.3 U10.137 | length 3228.3
  Top Layer w6: U10.137@4442.21,2221.07 4906.93,2221.07 4973,2155 v1(4973,1303)
  Bottom Layer w6: v1@4973,1304 5396,1304 5577,1123 5577,769 5568,760 5568,244.05 5614.05,198 5647,198 P2.3@5759,86
JTMS: P2.2 U10.124 | length 3313.2
  Top Layer w6: v1(4216,1282) 4216,1579.06 4210.06,1585 4210.06,1753.38 4235.52,1778.84 U10.124@4235.52,2093.12
  Bottom Layer w6: v1(4216,1282) 5389,1282 5554,1117 5554,782.32 5544,772.32 5544,201 P2.2@5659,86
MX_01: IO26.3 P16.3 | length 832.7
  Top Layer w10: IO26.3@2384.91,4754 2652.91,5022 2951,5022 P16.3@3061,5132
MX_02: IO28.3 P16.5 | length 732.4
  Top Layer w10: IO28.3@2585.18,4754 2797.18,4966 2995,4966 P16.5@3161,5132
MX_03: IO30.3 P16.7 | length 632.1
  Top Layer w10: IO30.3@2785.45,4754 2935.45,4904 3033,4904 P16.7@3261,5132
MX_04: IO32.3 P16.9 | length 533.4
  Top Layer w6: IO32.3@2985.73,4754 IO32.3@2985.73,4756.73
  Top Layer w10: IO32.3@2985.73,4756.73 P16.9@3361,5132
MX_05: IO34.3 P16.11 | length 490.5
  Top Layer w10: IO34.3@3187,4755 3187,4858 P16.11@3461,5132
MX_06: IO36.3 P16.13 | length 450.4
  Top Layer w10: IO36.3@3386.27,4754 3386.27,4915.27 3561,5090 P16.13@3561,5132
MX_07: IO38.3 P16.17 | length 450.3
  Top Layer w10: IO38.3@3586.55,4754 3586.55,4911.55 3761,5086 P16.17@3761,5132
MX_08: IO40.3 P16.19 | length 408.7
  Top Layer w10: IO40.3@3786.82,4754 3786.82,4988.82 3861,5063 P16.19@3861,5132
MX_09: IO27.3 P16.21 | length 388.8
  Top Layer w10: P16.21@3961,5132 3961,5105 3987.09,5078.91 IO27.3@3987.09,4754
MX_10: IO29.3 P16.23 | length 430.3
  Top Layer w10: P16.23@4061,5132 4187.36,5005.64 IO29.3@4187.36,4754
MX_11: IO31.3 P16.25 | length 471.9
  Top Layer w10: P16.25@4161,5132 4387.64,4905.36 IO31.3@4387.64,4754
MX_12: IO33.3 P16.27 | length 513.4
  Top Layer w10: P16.27@4261,5132 4587.91,4805.09 IO33.3@4587.91,4754
MX_13: IO35.3 P16.31 | length 513.5
  Top Layer w10: P16.31@4461,5132 4788.18,4804.82 IO35.3@4788.18,4754
MX_14: IO37.3 P16.33 | length 584
  Top Layer w10: P16.33@4561,5132 4787,4906 4836.45,4906 IO37.3@4988.45,4754
MX_15: IO39.3 P16.35 | length 684.3
  Top Layer w10: P16.35@4661,5132 4675,5132 4951,4856 5086.73,4856 IO39.3@5188.73,4754
MX_16: IO41.3 P16.37 | length 784.6
  Top Layer w10: P16.37@4761,5132 4976,4917 5226,4917 IO41.3@5389,4754
MX_ERR1: IO11.3 P15.9 | length 626.5
  Top Layer w10: IO11.3@2564.51,547.56 2710.07,402 2795.97,402 2930.53,267.44 2930.53,201.47 P15.9@2986,146
MX_ERR2: IO23.3 P15.10 | length 554.7
  Bottom Layer w10: IO23.3@2592.71,482.06 2592.71,371.29 2607,357 2840.97,357 2948.97,249 P15.10@2986,249
MX_ERR3: IO12.3 P15.23 | length 438.1
  Top Layer w10: P15.23@3686,146 3736,196 3736,274 3774.27,312.27 IO12.3@3774.27,547.56
MX_ERR4: IO24.3 P15.24 | length 280.3
  Bottom Layer w10: P15.24@3686,249 3686,343 3800.12,457.12 IO24.3@3800.12,482.06
MX_ERR5: IO13.3 P15.37 | length 807.1
  Top Layer w10: P15.37@4386,149 4437,200 4437,275 4604,442 4878.47,442 IO13.3@4984.03,547.56
MX_ERR6: IO25.3 P15.38 | length 718.1
  Bottom Layer w10: P15.38@4386,249 4506,369 4866.44,369 4979.51,482.06 IO25.3@5007.53,482.06
MX_HOM1: IO8.3 P15.7 | length 731
  Top Layer w10: IO8.3@2362.89,547.56 2537.45,373 2730,373 2841.47,261.53 2841.47,204.47 2886,159.95 P15.7@2886,146
MX_HOM2: IO20.3 P15.8 | length 664.6
  Bottom Layer w10: IO20.3@2391.47,482.06 2391.47,356.53 2411,337 2760.97,337 2848.97,249 P15.8@2886,249
MX_HOM3: IO9.3 P15.21 | length 432.9
  Top Layer w10: IO9.3@3572.65,547.56 3572.65,298.62 3541.47,267.44 3541.47,190.53 P15.21@3586,146
MX_HOM4: IO21.3 P15.22 | length 238.4
  Bottom Layer w10: P15.22@3586,249 3598.88,261.88 IO21.3@3598.88,482.06
MX_HOM5: IO10.3 P15.35 | length 704.3
  Top Layer w10: P15.35@4286,149 4335,198 4335,271 4536.56,472.56 4680.62,472.56 4755.62,547.56 IO10.3@4782.4,547.56
MX_HOM6: IO22.3 P15.36 | length 616.8
  Bottom Layer w10: P15.36@4286,249 4433,396 4720.23,396 IO22.3@4806.29,482.06
MX_LIM1+: IO2.3 P15.3 | length 931.3
  Top Layer w10: IO2.3@1959.64,547.56 2187.67,319.53 2578.44,319.53 2630.53,267.44 2630.53,238.47 2686,183 P15.3@2686,146
MX_LIM1-: IO5.3 P15.5 | length 829.7
  Top Layer w10: IO5.3@2161.26,547.56 2361.82,347 2650.97,347 2730.53,267.44 2730.53,201.47 P15.5@2786,146
MX_LIM2+: IO14.3 P15.4 | length 793.5
  Bottom Layer w10: IO14.3@1989,482.06 2174.06,297 2638,297 P15.4@2686,249
MX_LIM2-: IO17.3 P15.6 | length 779.8
  Bottom Layer w10: IO17.3@2190.24,482.06 2190.24,332.76 2206,317 2680.97,317 2748.97,249 P15.6@2786,249
MX_LIM3+: IO3.3 P15.17 | length 491.3
  Top Layer w10: IO3.3@3169.39,547.56 3169.39,438.61 3341.47,266.53 3341.47,204.47 3386,159.95 P15.17@3386,146
MX_LIM3-: IO6.3 P15.19 | length 449.2
  Top Layer w10: IO6.3@3371.02,547.56 3371.02,326.95 3430.53,267.44 3430.53,201.47 P15.19@3486,146
MX_LIM4+: IO15.3 P15.18 | length 311.6
  Bottom Layer w10: IO15.3@3196.41,482.06 3196.41,438.59 P15.18@3386,249
MX_LIM4-: IO18.3 P15.20 | length 269.7
  Bottom Layer w10: IO18.3@3397.65,482.06 3397.65,337.35 P15.20@3486,249
MX_LIM5+: IO4.3 P15.31 | length 520
  Top Layer w10: P15.31@4086,149 4086,159.95 4130.53,204.47 4130.53,298.94 IO4.3@4379.15,547.56
MX_LIM5-: IO7.3 P15.33 | length 596.8
  Top Layer w10: P15.33@4186,149 4186,179.57 4238,231.57 4238,263.97 4267.56,293.53 4299.96,293.53 4553.99,547.56 IO7.3@4580.78,547.56
MX_LIM6+: IO16.3 P15.32 | length 414.4
  Bottom Layer w10: P15.32@4086,249 4098,249 4276.06,427.06 4320.8,427.06 4375.8,482.06 IO16.3@4403.82,482.06
MX_LIM6-: IO19.3 P15.34 | length 515.6
  Bottom Layer w10: P15.34@4186,249 4364.06,427.06 4522.04,427.06 4577.04,482.06 IO19.3@4605.06,482.06
NetC3_1: C3.1 U2.1 | length 123.2
  Bottom Layer w30: U2.1@5687.19,3853 5688.19,3852 C3.1@5809.94,3852
NetC3_2: C3.2 D2.2 U1.2 U2.8 | length 1806.1
  Top Layer w40: v9@5209,3526 5209,3854 5333,3978 5477,3978 5520,3935 5681,3935 v9(5690,3944)
  Bottom Layer w40: U1.2@4740.32,3823.43 4815.75,3748 4936.64,3748 5015.64,3669 5027,3669 5170,3526 v9(5208,3526) v9@5208,3534 ; v9@5385,3983 5386,3982 D2.2@5459.65,3982 5460.81,3980.84 U2.8@5460.81,3853 ; v9(5690,3944) 5692,3942 C3.2@5809.94,3942
  other v9: 5376,3987
NetC6_2: C6.2 R2.1 | length 103.7
  Bottom Layer w30: C6.2@5241.06,3734 5241.06,3633 R2.1@5243,3631.06
NetC11_1: C11.1 U3.1 | length 78.1
  Bottom Layer w30: C11.1@5581.75,3248 5581.75,3170.25 U3.1@5582,3170
NetC11_2: C11.2 D3.2 L1.1 U3.8 | length 1231.4
  Top Layer w40: v9@5378,3262 5385,3255 5573,3255 5639,3321 v9(5639,3340)
  Bottom Layer w40: L1.1@4668.46,3332.65 D3.2@4792,3332.65 4792,3314.46 4886.46,3220 5253.3,3220 5303.3,3170 U3.8@5355.62,3170 5355.62,3237.62 v9(5377,3259) ; C11.2@5581.75,3338 5637,3338 v9(5639,3340)
NetC13_2: C13.2 R5.1 | length 98.4
  Bottom Layer w30: R5.1@5122.81,2969.06 5123.88,2970.13 C13.2@5123.88,3067
NetC14_2: C14.2 R5.2 U3.6 | length 242
  Bottom Layer w30: R5.2@5212.81,2969.06 5215.88,2972.13 C14.2@5215.88,3070 U3.6@5355.62,3070
NetC19_1: C19.1 L2.1 U4.2 U4.4 | length 637.8
  Bottom Layer w20: U4.2@4807.45,2562.13 U4.4@4807.45,2821.97 4932.03,2821.97 4954,2800 C19.1@5034,2800 5158.27,2800 L2.1@5171,2787.27
NetC20_2: C20.2 L3.2 | length 93.6
  Bottom Layer w20: L3.2@5264,2697.27 5264,2605.06 C20.2@5265,2604.06
NetC22_2: C22.2 D5.2 F1.2 R13.2 U5.1 | length 1040.4
  Top Layer w50: D5.2@5802.85,4526.57 F1.2@5802.85,4651 ; D5.2@5804.43,4525 5760.43,4481.01 R13.2@5760.43,4428 5782,4406.43 C22.2@5782,4330.94 5856.94,4330.94 5903,4377 5903,4786 U5.1@6006,4889
NetC27_2: C27.2 D7.2 IO1.1 R17.2 R19.2 | length 682.3
  Top Layer w10: IO1.1@5488.91,547.56 5515.69,547.56 5570.69,602.56 5607.12,602.56 5624.68,585 R17.2@5838.06,585 C27.2@5933.06,585 5969.8,621.74 D7.2@6023,621.74 6085.32,621.74 R19.2@6114.06,593
NetC29_2: C29.2 R21.1 U10.29 Y1.1 | length 898.5
  Top Layer w6: U10.29@3841.82,3038 3841.82,3582.82 3878,3619 3925,3666 Y1.1@3925,3777
  Top Layer w10: R21.1@3878,3619 C29.2@4003,3619
NetC30_2: C30.2 R21.2 U10.30 Y1.2 | length 896
  Top Layer w6: Y1.2@3732.87,3777 3732.87,3674.19 R21.2@3788,3619.06 3788,3615.69 3822.14,3581.56 U10.30@3822.14,3038
  Top Layer w10: C30.2@3663,3619 R21.2@3783,3619
NetC31_2: C31.2 U10.125 | length 378.1
  Top Layer w6: C31.2@4248.06,1718 4255.2,1725.14 U10.125@4255.2,2093.12
NetC32_2: C32.2 U10.81 | length 321.1
  Top Layer w6: C32.2@3196,2327.94 3266.44,2327.94 3314.25,2280.13 U10.81@3497.33,2280.13
NetC97_2: C97.2 R165.2 U54.1 | length 260.8
  Top Layer w10: U54.1@2766.14,795.56 2766.14,915.14 2775.82,924.82 C97.2@2775.82,953.94 R165.2@2775.82,1052.38
NetC98_2: C98.2 R166.2 U55.1 | length 260.8
  Top Layer w8: U55.1@2967.77,795.56 2967.77,915.77 2977.27,925.27 C98.2@2977.27,953.94 R166.2@2977.27,1052.38
NetC99_2: C99.2 R167.2 U56.1 | length 255.6
  Bottom Layer w10: U56.1@2793.94,730.06 2793.94,882.94 C99.2@2798,887 2798.06,887.06 R167.2@2798.06,984
NetC100_2: C100.2 R168.2 U57.1 | length 255.9
  Bottom Layer w10: U57.1@2995.18,730.06 2995.18,881.53 2999.82,886.18 R168.2@2999.82,984
NetC101_2: C101.2 R169.2 U58.1 | length 260.4
  Top Layer w10: U58.1@3975.9,795.56 3975.9,914.9 3984.55,923.55 C101.2@3984.55,953.94 R169.2@3984.55,1052.38
NetC102_2: C102.2 R170.2 U59.1 | length 260.3
  Top Layer w10: U59.1@4177.52,795.56 4177.52,926.52 4186,935 C102.2@4186,953.94 R170.2@4186,1052.38
NetC104_2: C104.2 R171.2 U60.1 | length 253.2
  Bottom Layer w10: U60.1@4001.35,730.06 4001.35,881.35 C104.2@4006,886 ; C104.2@4008.65,888.65 R171.2@4008.65,984
NetC105_2: C105.2 R172.2 U61.1 | length 253.8
  Bottom Layer w10: U61.1@4202.59,730.06 4202.59,880.59 C105.2@4208,886 ; C105.2@4210.41,888.41 R172.2@4210.41,984
NetC107_2: C107.2 R173.2 U62.1 | length 262.4
  Top Layer w10: U62.1@5185.66,795.56 5185.66,916.66 5194.27,925.27 C107.2@5194.27,955.94 R173.2@5194.27,1054.38
NetC108_2: C108.2 R174.2 U63.1 | length 262.3
  Top Layer w10: U63.1@5387.28,795.56 5387.28,897.28 5395.73,905.73 C108.2@5395.73,955.94 R174.2@5395.73,1054.38
NetC109_2: C109.2 R175.2 U64.1 | length 258.3
  Bottom Layer w10: U64.1@5208.76,730.06 5208.76,876.02 5219.23,886.49 R175.2@5219.23,984
NetC110_2: C110.2 R176.2 U65.1 | length 258.5
  Bottom Layer w10: U65.1@5410,730.06 5410,875 C110.2@5421,886 R176.2@5421,984
NetC113_2: C113.2 R181.2 U66.1 | length 217.1
  Bottom Layer w10: R181.2@2956.09,4279.06 C113.2@2956.09,4382.06 2966.09,4392.06 U66.1@2966.09,4492
NetC114_2: C114.2 R182.2 U67.1 | length 216.6
  Bottom Layer w10: R182.2@3157.64,4279.06 3157.64,4382.25 3166.36,4390.97 U67.1@3166.36,4492
NetC115_2: C115.2 R185.2 U68.1 | length 216
  Bottom Layer w10: R185.2@3359.18,4279.06 3359.18,4382.43 3366.64,4389.88 U68.1@3366.64,4492
NetC116_2: C116.2 R186.2 U69.1 | length 215.5
  Bottom Layer w10: R186.2@3560.73,4279.06 3566.91,4285.25 U69.1@3566.91,4492
NetC119_2: C119.2 R189.2 U70.1 | length 215
  Bottom Layer w10: R189.2@3762.27,4279.06 3767.18,4283.97 U70.1@3767.18,4492
NetC120_2: C120.2 R190.2 U71.1 | length 214.4
  Bottom Layer w10: R190.2@3963.82,4279.06 3967.45,4282.7 U71.1@3967.45,4492
NetC123_2: C123.2 R195.2 U72.1 | length 213.9
  Bottom Layer w10: R195.2@4165.36,4279.06 4167.73,4281.43 U72.1@4167.73,4492
NetC124_2: C124.2 R196.2 U73.1 | length 213.4
  Bottom Layer w10: R196.2@4366.91,4279.06 4368,4280.16 U73.1@4368,4492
